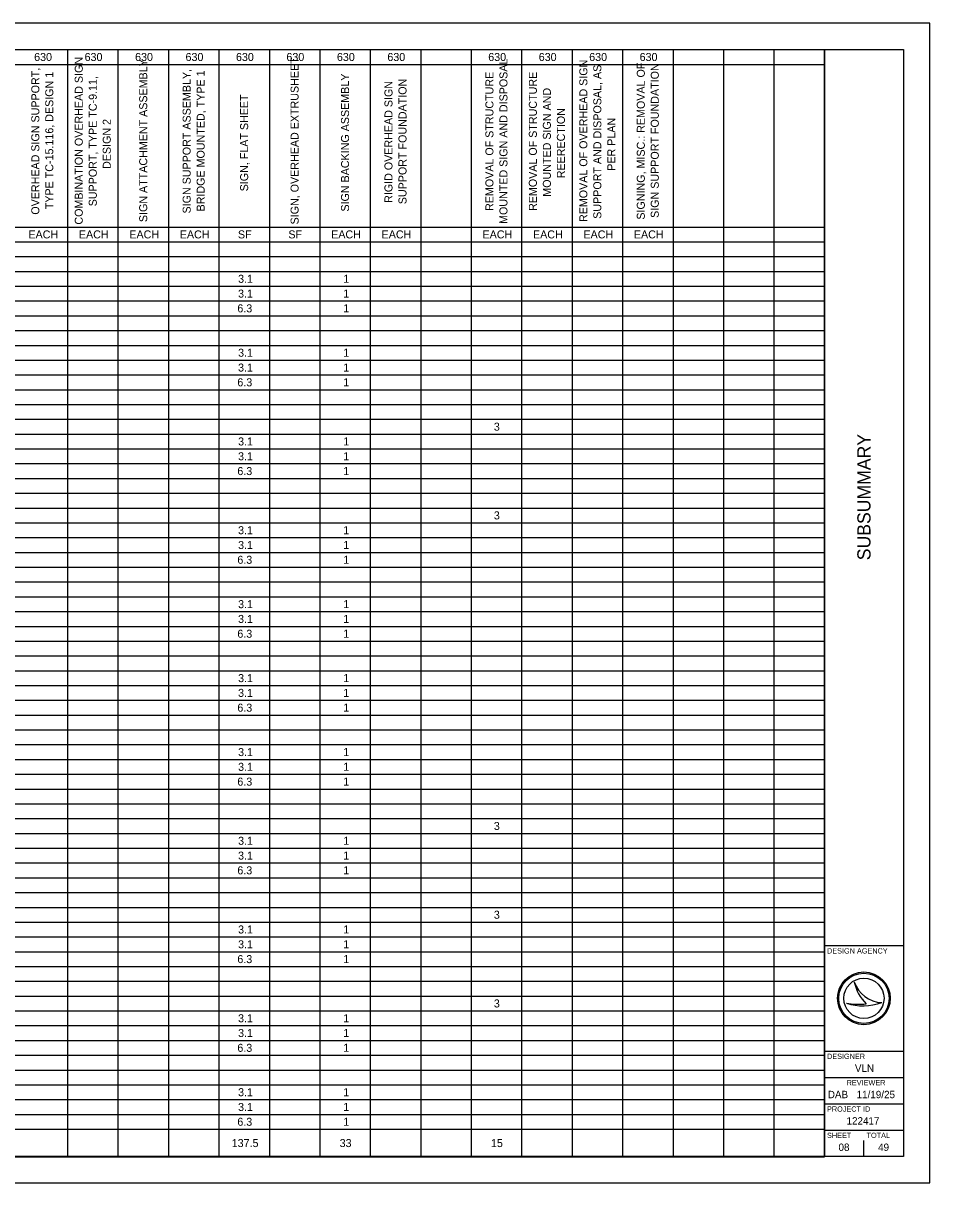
# Model space of a CAD drawing. Extents: x 0 to 34, y 0 to 22.
# Drawn here: x 16.8 to 34, y 0 to 22 of the extents above; entities that cross this region are included whole.
import ezdxf

# ---------------------------------------------------------------- set-up
doc = ezdxf.new("R2010")
doc.units = 0
for name, color, linetype in [('SH_Border', 7, 'Continuous'), ('SH_Cut_Line', 7, 'Continuous'), ('SH_Data', 7, 'Continuous'), ('SH_Text', 7, 'Continuous')]:
    doc.layers.add(name, color=color, linetype=linetype)

msp = doc.modelspace()

# ---------------------------------------------------------------- linework, layer by layer
at = {"layer": 'SH_Border'}
for p, q in [((32, 0.5), (32, 21.5)), ((32, 4.5), (33.5, 4.5)), ((32, 2.5), (33.5, 2.5)), ((32, 2), (33.5, 2)), ((32, 1.5), (33.5, 1.5)), ((32, 1), (33.5, 1))]:
    msp.add_line(p, q, dxfattribs=at)
msp.add_lwpolyline([(1.5, 21.5), (33.5, 21.5), (33.5, 0.5), (1.5, 0.5)], close=True, dxfattribs=at)
at = {"layer": 'SH_Cut_Line'}
msp.add_lwpolyline([(0, 0), (34, 0), (34, 22), (0, 22)], close=True, dxfattribs=at)
at = {"layer": 'SH_Data'}
for p, q in [((32.567, 3.81), (32.567, 3.81)), ((32.417, 3.41), (32.417, 3.41)), ((32.75, 3.5), (32.75, 3.5)), ((33.087, 3.419), (33.087, 3.419)), ((32.375, 0.675), (32.375, 0.675)), ((32.75, 0.5), (32.75, 0.8))]:
    msp.add_line(p, q, dxfattribs=at)
for radius in [0.5, 0.477, 0.477, 0.382]:
    msp.add_circle((32.75, 3.5), radius, dxfattribs=at)
for centre, radius, start, end in [((33.116, 3.998), 0.58, 198.9257, 198.9319), ((33.347, 3.97), 0.796, 191.6379, 191.6421), ((33.116, 3.998), 0.58, 198.9319, 267.1657), ((33.347, 3.97), 0.796, 191.6421, 226.0947), ((32.739, 4.37), 1.013, 251.4576, 290.0832), ((32.648, 4.654), 1.266, 259.4964, 259.4995), ((32.739, 4.37), 1.013, 251.4527, 251.4576), ((32.648, 4.654), 1.266, 259.4995, 276.6672)]:
    msp.add_arc(centre, radius, start, end, dxfattribs=at)
at = {"layer": 'SH_Text'}
for p, q in [((1.5, 21.5), (32, 21.5)), ((17.641, 21.5), (17.641, 0.49)), ((18.598, 21.5), (18.598, 0.49)), ((19.556, 21.5), (19.556, 0.49)), ((20.513, 21.5), (20.513, 0.49)), ((21.47, 21.5), (21.47, 0.49)), ((22.427, 21.5), (22.427, 0.49)), ((23.385, 21.5), (23.385, 0.49)), ((24.342, 21.5), (24.342, 0.49)), ((25.299, 21.5), (25.299, 0.49)), ((26.256, 21.5), (26.256, 0.49)), ((27.214, 21.5), (27.214, 0.49)), ((28.171, 21.5), (28.171, 0.49)), ((29.128, 21.5), (29.128, 0.49)), ((30.085, 21.5), (30.085, 0.49)), ((31.043, 21.5), (31.043, 0.49)), ((32, 21.5), (32, 0.49)), ((9.983, 21.219), (32, 21.219)), ((9.983, 18.133), (32, 18.133)), ((1.5, 17.852), (32, 17.852)), ((1.5, 17.572), (32, 17.572)), ((1.5, 17.291), (32, 17.291)), ((7.739, 17.01), (32, 17.01)), ((7.739, 16.73), (32, 16.73)), ((1.5, 16.449), (32, 16.449)), ((1.5, 16.169), (32, 16.169)), ((1.5, 15.888), (32, 15.888)), ((7.739, 15.608), (32, 15.608)), ((7.739, 15.327), (32, 15.327)), ((1.5, 15.046), (32, 15.046)), ((1.5, 14.766), (32, 14.766)), ((1.5, 14.485), (32, 14.485)), ((7.739, 14.205), (32, 14.205)), ((7.739, 13.924), (32, 13.924)), ((7.739, 13.644), (32, 13.644)), ((1.5, 13.363), (32, 13.363)), ((1.5, 13.082), (32, 13.082)), ((1.5, 12.802), (32, 12.802)), ((7.739, 12.521), (32, 12.521)), ((7.739, 12.241), (32, 12.241)), ((7.739, 11.96), (32, 11.96)), ((1.5, 11.68), (32, 11.68)), ((1.5, 11.399), (32, 11.399)), ((1.5, 11.118), (32, 11.118)), ((7.739, 10.838), (32, 10.838)), ((7.739, 10.557), (32, 10.557)), ((1.5, 10.277), (32, 10.277)), ((1.5, 9.996), (32, 9.996)), ((1.5, 9.716), (32, 9.716)), ((7.739, 9.435), (32, 9.435)), ((7.739, 9.154), (32, 9.154)), ((1.5, 8.874), (32, 8.874)), ((1.5, 8.593), (32, 8.593)), ((1.5, 8.313), (32, 8.313)), ((7.739, 8.032), (32, 8.032)), ((7.739, 7.752), (32, 7.752)), ((1.5, 7.471), (32, 7.471)), ((1.5, 7.19), (32, 7.19)), ((1.5, 6.91), (32, 6.91)), ((7.739, 6.629), (32, 6.629)), ((7.739, 6.349), (32, 6.349)), ((7.739, 6.068), (32, 6.068)), ((1.5, 5.788), (32, 5.788)), ((1.5, 5.507), (32, 5.507)), ((1.5, 5.226), (32, 5.226)), ((7.739, 4.946), (32, 4.946)), ((7.739, 4.665), (32, 4.665)), ((7.739, 4.385), (32, 4.385)), ((1.5, 4.104), (32, 4.104)), ((1.5, 3.823), (32, 3.823)), ((1.5, 3.543), (32, 3.543)), ((7.739, 3.262), (32, 3.262)), ((7.739, 2.982), (32, 2.982)), ((7.739, 2.701), (32, 2.701)), ((1.5, 2.421), (32, 2.421)), ((1.5, 2.14), (32, 2.14)), ((1.5, 1.859), (32, 1.859)), ((7.739, 1.579), (32, 1.579)), ((7.739, 1.298), (32, 1.298)), ((1.5, 1.018), (32, 1.018)), ((1.5, 0.49), (32, 0.49))]:
    msp.add_line(p, q, dxfattribs=at)

# ---------------------------------------------------------------- texts
at = {"layer": 'SH_Data'}
msp.add_text('SUBSUMMARY', height=0.25, rotation=90, dxfattribs=at).set_placement((32.875, 11.811))
for s, height, p in [('DESIGN AGENCY', 0.1, (32.05, 4.35)), ('DESIGNER', 0.1, (32.05, 2.35)), ('VLN', 0.14, (32.579, 2.105)), ('REVIEWER', 0.1, (32.422, 1.85)), ('DAB', 0.14, (32.065, 1.605)), ('11/19/25', 0.14, (32.611, 1.605)), ('PROJECT ID', 0.1, (32.05, 1.35)), ('122417', 0.14, (32.42, 1.105)), ('SHEET', 0.1, (32.05, 0.85)), ('TOTAL', 0.1, (32.8, 0.85)), ('08', 0.14, (32.268, 0.605)), ('49', 0.14, (33.019, 0.605))]:
    msp.add_text(s, height=height, dxfattribs=at).set_placement(p)
at = {"layer": 'SH_Text'}
for s, height, p in [('630', 0.1518, (17.008, 21.283)), ('630', 0.1518, (17.965, 21.283)), ('630', 0.1518, (18.923, 21.283)), ('630', 0.1518, (19.88, 21.283)), ('630', 0.1518, (20.837, 21.283)), ('630', 0.1518, (21.794, 21.283)), ('630', 0.1518, (22.752, 21.283)), ('630', 0.1518, (23.709, 21.283)), ('630', 0.1518, (25.623, 21.283)), ('630', 0.1518, (26.581, 21.283)), ('630', 0.1518, (27.538, 21.283)), ('630', 0.1518, (28.495, 21.283)), ('EACH', 0.1518, (16.899, 17.917)), ('EACH', 0.1518, (17.857, 17.917)), ('EACH', 0.1518, (18.814, 17.917)), ('EACH', 0.1518, (19.771, 17.917)), ('SF', 0.1518, (20.874, 17.917)), ('SF', 0.1518, (21.831, 17.917)), ('EACH', 0.1518, (22.643, 17.917)), ('EACH', 0.1518, (23.6, 17.917)), ('EACH', 0.1518, (25.515, 17.917)), ('EACH', 0.1518, (26.472, 17.917)), ('EACH', 0.1518, (27.429, 17.917)), ('EACH', 0.1518, (28.386, 17.917)), ('3.1', 0.1518, (20.877, 17.075)), ('1', 0.152, (22.871, 17.075)), ('3.1', 0.1518, (20.877, 16.794)), ('1', 0.152, (22.871, 16.794)), ('6.3', 0.1518, (20.863, 16.514)), ('1', 0.152, (22.871, 16.514)), ('3.1', 0.1518, (20.877, 15.672)), ('1', 0.152, (22.871, 15.672)), ('3.1', 0.1518, (20.877, 15.391)), ('1', 0.152, (22.871, 15.391)), ('6.3', 0.1518, (20.863, 15.111)), ('1', 0.152, (22.871, 15.111)), ('3', 0.152, (25.729, 14.269)), ('3.1', 0.1518, (20.877, 13.989)), ('1', 0.152, (22.871, 13.989)), ('3.1', 0.1518, (20.877, 13.708)), ('1', 0.152, (22.871, 13.708)), ('6.3', 0.1518, (20.863, 13.427)), ('1', 0.152, (22.871, 13.427)), ('3', 0.152, (25.729, 12.586)), ('3.1', 0.1518, (20.877, 12.305)), ('1', 0.152, (22.871, 12.305)), ('3.1', 0.1518, (20.877, 12.024)), ('1', 0.152, (22.871, 12.024)), ('6.3', 0.1518, (20.863, 11.744)), ('1', 0.152, (22.871, 11.744)), ('3.1', 0.1518, (20.877, 10.902)), ('1', 0.152, (22.871, 10.902)), ('3.1', 0.1518, (20.877, 10.622)), ('1', 0.152, (22.871, 10.622)), ('6.3', 0.1518, (20.863, 10.341)), ('1', 0.152, (22.871, 10.341)), ('3.1', 0.1518, (20.877, 9.499)), ('1', 0.152, (22.871, 9.499)), ('3.1', 0.1518, (20.877, 9.219)), ('1', 0.152, (22.871, 9.219)), ('6.3', 0.1518, (20.863, 8.938)), ('1', 0.152, (22.871, 8.938)), ('3.1', 0.1518, (20.877, 8.096)), ('1', 0.152, (22.871, 8.096)), ('3.1', 0.1518, (20.877, 7.816)), ('1', 0.152, (22.871, 7.816)), ('6.3', 0.1518, (20.863, 7.535)), ('1', 0.152, (22.871, 7.535)), ('3', 0.152, (25.729, 6.694)), ('3.1', 0.1518, (20.877, 6.413)), ('1', 0.152, (22.871, 6.413)), ('3.1', 0.1518, (20.877, 6.132)), ('1', 0.152, (22.871, 6.132)), ('6.3', 0.1518, (20.863, 5.852)), ('1', 0.152, (22.871, 5.852)), ('3', 0.152, (25.729, 5.01)), ('3.1', 0.1518, (20.877, 4.73)), ('1', 0.152, (22.871, 4.73)), ('3.1', 0.1518, (20.877, 4.449)), ('1', 0.152, (22.871, 4.449)), ('6.3', 0.1518, (20.863, 4.168)), ('1', 0.152, (22.871, 4.168)), ('3', 0.152, (25.729, 3.327)), ('3.1', 0.1518, (20.877, 3.046)), ('1', 0.152, (22.871, 3.046)), ('3.1', 0.1518, (20.877, 2.766)), ('1', 0.152, (22.871, 2.766)), ('6.3', 0.1518, (20.863, 2.485)), ('1', 0.152, (22.871, 2.485)), ('3.1', 0.1518, (20.877, 1.643)), ('1', 0.152, (22.871, 1.643)), ('3.1', 0.1518, (20.877, 1.363)), ('1', 0.152, (22.871, 1.363)), ('6.3', 0.1518, (20.863, 1.082)), ('1', 0.152, (22.871, 1.082)), ('137.5', 0.1518, (20.756, 0.678)), ('33', 0.1518, (22.804, 0.678)), ('15', 0.1518, (25.675, 0.678))]:
    msp.add_text(s, height=height, dxfattribs=at).set_placement(p)
for s, height, p in [('COMBINATION OVERHEAD SIGN ', 0.15184, (17.93, 18.179)), ('SIGN, OVERHEAD EXTRUSHEET', 0.15184, (22.025, 18.182)), ('OVERHEAD SIGN SUPPORT, ', 0.15184, (17.106, 18.367)), ('SIGN ATTACHMENT ASSEMBLY', 0.15184, (19.153, 18.226)), ('MOUNTED SIGN AND DISPOSAL', 0.15184, (25.987, 18.192)), ('REMOVAL OF OVERHEAD SIGN ', 0.15184, (27.503, 18.228)), ('SUPPORT AND DISPOSAL, AS ', 0.15184, (27.768, 18.289)), ('SIGNING, MISC.: REMOVAL OF ', 0.15184, (28.593, 18.273)), ('SIGN SUPPORT FOUNDATION', 0.15184, (28.858, 18.306)), ('TYPE TC-15.116, DESIGN 1', 0.15184, (17.371, 18.471)), ('SUPPORT, TYPE TC-9.11, ', 0.15184, (18.196, 18.526)), ('SIGN SUPPORT ASSEMBLY, ', 0.15184, (19.977, 18.39)), ('BRIDGE MOUNTED, TYPE 1', 0.15184, (20.243, 18.429)), ('SIGN BACKING ASSEMBLY', 0.15184, (22.982, 18.426)), ('SUPPORT FOUNDATION', 0.15184, (24.072, 18.566)), ('REMOVAL OF STRUCTURE ', 0.15184, (25.721, 18.438)), ('REMOVAL OF STRUCTURE ', 0.15184, (26.545, 18.438)), ('RIGID OVERHEAD SIGN ', 0.15184, (23.806, 18.591)), ('MOUNTED SIGN AND ', 0.15184, (26.811, 18.708)), ('SIGN, FLAT SHEET', 0.15184, (21.068, 18.81)), ('REERECTION', 0.1518, (27.077, 19.058)), ('DESIGN 2', 0.1518, (18.461, 19.235)), ('PER PLAN', 0.1518, (28.034, 19.201))]:
    msp.add_text(s, height=height, rotation=90, dxfattribs=at).set_placement(p)

doc.saveas('drawing.dxf')
